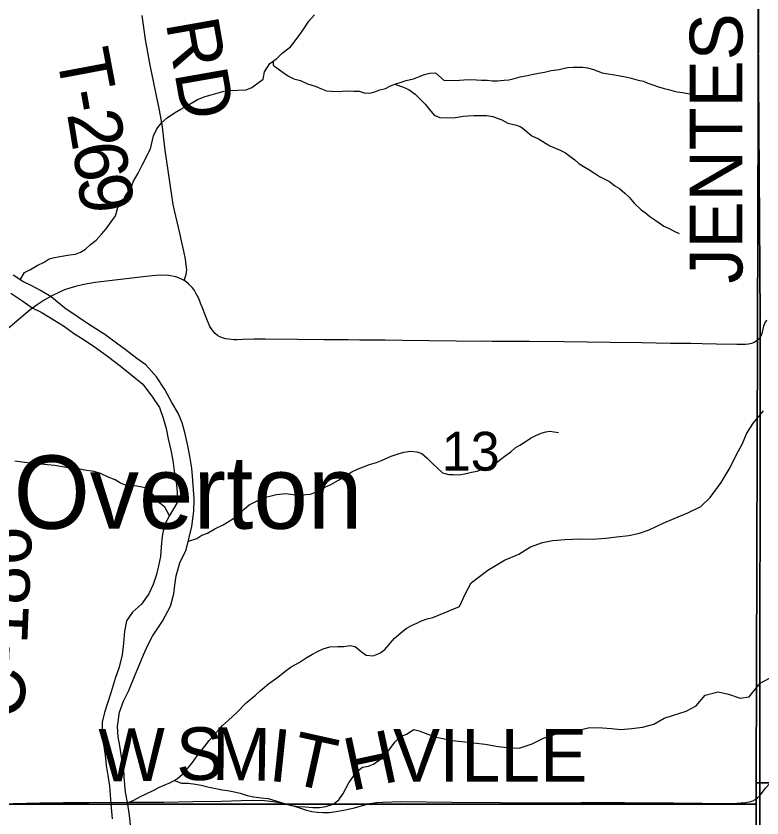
# Model space of a CAD drawing. Extents: x 1985906 to 2360102, y 891258 to 1222054.
# Drawn here: x 2104398 to 2108640, y 1041341 to 1045904 of the extents above; entities that cross this region are included whole.
import ezdxf

# ---------------------------------------------------------------- set-up
doc = ezdxf.new("R2010")
doc.units = 0
for name, color, linetype in [('GM_X_County_Road', 7, 'Continuous'), ('GM_X_County_Road_Text', 7, 'Continuous'), ('GM_X_Major_River', 7, 'Continuous'), ('GM_X_Minor_River', 7, 'Continuous'), ('GM_X_Section', 7, 'Continuous'), ('GM_X_Section_Text', 7, 'Continuous'), ('GM_X_Township', 7, 'Continuous'), ('GM_X_Township_Road', 7, 'Continuous'), ('GM_X_Township_Road_Text', 7, 'Continuous'), ('GM_X_Unincorporated_Text', 7, 'Continuous')]:
    doc.layers.add(name, color=color, linetype=linetype)

msp = doc.modelspace()

# ---------------------------------------------------------------- linework, layer by layer
at = {"layer": 'GM_X_County_Road'}
for points in [[(2105354.5, 1044398.9), (2105331, 1044411), (2105305.9, 1044419.7), (2105265.9, 1044427.5), (2105217.3, 1044429.3), (2105171.3, 1044426.7), (2105119.9, 1044420.4), (2105008.4, 1044407.9), (2104960.2, 1044402.4), (2104911.8, 1044396.6), (2104847, 1044388), (2104782.8, 1044376.9), (2104735.4, 1044366), (2104704.4, 1044356.9), (2104674.1, 1044346), (2104644.3, 1044333.8), (2104600.5, 1044312.2), (2104558, 1044288.1), (2104517.1, 1044261.3), (2104478.1, 1044231.8), (2104390.3, 1044158.3), (2104337.5, 1044113)], [(2105453.9, 1044254.4), (2105453.5, 1044255.6), (2105437, 1044296.4), (2105423.1, 1044324.2), (2105410, 1044345.9), (2105399.6, 1044359.8), (2105379.6, 1044379.8), (2105358, 1044397.1), (2105354.5, 1044398.9)], [(2108628.4, 1044074.7), (2108623.7, 1044068), (2108611.2, 1044056.2), (2108596.7, 1044047.3), (2108580.8, 1044041.2), (2108564.1, 1044037.8), (2108547.4, 1044035.8), (2108497.5, 1044034.6), (2108382.7, 1044037.3), (2108300.8, 1044039.2), (2108235.4, 1044040.3), (2108120.8, 1044041.9), (2107957.3, 1044044.9), (2107777.1, 1044047.1), (2107515.1, 1044050.3), (2107319, 1044052.2), (2107106.6, 1044053.4), (2107073.9, 1044053.5), (2107057.5, 1044053.1), (2106746.3, 1044055.9), (2106596.1, 1044058.2), (2106498, 1044059.2), (2106406.8, 1044060.1), (2106353, 1044060.6), (2106286.1, 1044061.3), (2106215.8, 1044062), (2106148.1, 1044062.7), (2105998.7, 1044064.2), (2105815.1, 1044066), (2105751.5, 1044065), (2105688.3, 1044063.9), (2105655.5, 1044062.7), (2105639, 1044062.9), (2105605.7, 1044065.5), (2105589.2, 1044068.1), (2105572.9, 1044072.5), (2105557.3, 1044078.7), (2105543, 1044087.5), (2105530, 1044098.2), (2105518.6, 1044110.5), (2105508.6, 1044123.9), (2105499.9, 1044138), (2105479.5, 1044188.7), (2105453.9, 1044254.4)], [(2108669.1, 1044174.3), (2108666.2, 1044171.8), (2108659.4, 1044162.3), (2108654.3, 1044153), (2108650, 1044140), (2108640.2, 1044097.9), (2108633.7, 1044082.2), (2108628.4, 1044074.7)]]:
    msp.add_lwpolyline(points, dxfattribs=at)
at = {"layer": 'GM_X_Major_River'}
for points in [[(2105050.1, 1041285), (2105043.7, 1041355), (2105033.4, 1041419.1), (2105021, 1041489.1), (2105012.5, 1041573.2), (2105010.3, 1041623.2), (2104997.9, 1041689.2), (2104987.6, 1041751.3), (2104979.3, 1041803.3), (2104974.9, 1041861.3), (2104986.5, 1041943.5), (2105008.2, 1042005.8), (2105039.8, 1042066), (2105075.3, 1042156.3), (2105099, 1042214.6), (2105122.7, 1042268.8), (2105146.4, 1042325), (2105174.1, 1042375.2), (2105231.6, 1042461.7), (2105277.2, 1042546.1), (2105294.8, 1042616.3), (2105300.5, 1042666.4), (2105308.2, 1042718.5), (2105329.8, 1042792.7), (2105365.4, 1042867.1), (2105383, 1042937.2), (2105396.7, 1042999.4), (2105408.2, 1043087.6), (2105411.8, 1043155.7), (2105407.5, 1043209.8), (2105403.2, 1043261.8), (2105396.8, 1043331.9), (2105386.5, 1043399.9), (2105374.2, 1043457.9), (2105359.8, 1043528), (2105343.4, 1043589.9), (2105319.1, 1043643.9), (2105284.8, 1043705.8), (2105244.4, 1043779.7), (2105196, 1043851.5), (2105135.6, 1043919.2), (2105085.4, 1043955), (2105019.2, 1044006.7), (2104969, 1044042.4), (2104902.7, 1044092.1), (2104816.4, 1044147.7), (2104675.9, 1044243), (2104597.6, 1044306.6), (2104537.4, 1044342.3), (2104487.2, 1044370.1), (2104437.1, 1044393.8), (2104380.9, 1044429.5)], [(2104367.5, 1044327.3), (2104435.7, 1044281.6), (2104489.9, 1044243.9), (2104540, 1044220.2), (2104618.3, 1044172.5), (2104672.5, 1044138.8), (2104724.7, 1044099.1), (2104778.9, 1044065.3), (2104855.1, 1044013.7), (2104925.4, 1043964), (2104989.7, 1043914.3), (2105047.9, 1043866.6), (2105118.3, 1043808.9), (2105174.7, 1043735.2), (2105213, 1043677.3), (2105237.3, 1043611.4), (2105251.6, 1043557.4), (2105263.9, 1043499.3), (2105278.3, 1043433.3), (2105288.6, 1043375.3), (2105296.9, 1043315.3), (2105309.3, 1043253.3), (2105313.6, 1043195.2), (2105311.9, 1043133.1), (2105268.4, 1043058.8), (2105242.6, 1043008.5), (2105229, 1042944.4), (2105223.3, 1042884.2), (2105219.6, 1042828.2), (2105207.9, 1042776), (2105196.2, 1042725.9), (2105178.5, 1042669.7), (2105152.8, 1042617.5), (2105111.1, 1042557.1), (2105059.4, 1042512.8), (2105025.6, 1042462.5), (2105014, 1042404.3), (2105008.3, 1042336.2), (2105000.7, 1042270.1), (2104985.1, 1042199.9), (2104961.4, 1042135.7), (2104937.9, 1042059.4), (2104918.2, 1041995.2), (2104900.5, 1041941), (2104886.8, 1041886.9), (2104887.2, 1041816.8), (2104895.5, 1041760.7), (2104903.8, 1041698.7)], [(2104903.8, 1041698.7), (2104910.2, 1041640.7), (2104920.5, 1041582.6), (2104928.8, 1041524.6), (2104933.1, 1041470.6), (2104939.5, 1041398.5), (2104943.8, 1041336.4)]]:
    msp.add_lwpolyline(points, dxfattribs=at)
at = {"layer": 'GM_X_Minor_River'}
for points in [[(2104421.4, 1044403.8), (2104446.2, 1044445.7), (2104480.1, 1044461.9), (2104518.1, 1044484.2), (2104558.1, 1044504.4), (2104586, 1044522.6), (2104616, 1044530.8), (2104658.1, 1044539), (2104704.1, 1044545.2), (2104736.2, 1044549.4), (2104764.2, 1044561.6), (2104792.1, 1044577.8), (2104822.1, 1044604), (2104854, 1044628.2), (2104883.9, 1044662.5), (2104909.8, 1044692.7), (2104929.7, 1044720.9), (2104963.5, 1044767.3), (2104977.3, 1044815.5), (2105003.2, 1044845.8), (2105021, 1044884), (2105050.8, 1044922.3), (2105066.7, 1044964.5), (2105092.5, 1045010.8), (2105116.3, 1045059.1), (2105132.1, 1045087.3), (2105146, 1045117.4), (2105161.9, 1045149.6), (2105179.5, 1045222), (2105199.4, 1045262.2), (2105225.2, 1045296.5), (2105257.1, 1045324.7), (2105299.1, 1045353), (2105335, 1045375.3), (2105369, 1045393.5), (2105428.9, 1045429.9), (2105472.9, 1045446.2), (2105506.9, 1045456.4), (2105547, 1045466.6), (2105581, 1045476.8), (2105609, 1045480.9), (2105659.1, 1045483.2), (2105707.2, 1045485.4), (2105739.2, 1045497.6), (2105775.1, 1045523.8), (2105803, 1045546.1), (2105810.9, 1045586.3), (2105840.7, 1045634.6), (2105880.6, 1045662.9), (2105910.5, 1045693.1), (2105958.4, 1045729.5), (2105986.3, 1045763.7), (2106012.1, 1045800), (2106034, 1045832.2), (2106063.8, 1045874.5), (2106095.7, 1045910.8)], [(2105859.9, 1045648.2), (2105860.7, 1045624.6), (2105917.1, 1045582.7), (2105947.2, 1045562.8), (2105977.4, 1045546.9), (2106015.5, 1045537), (2106055.7, 1045519.1), (2106099.8, 1045505.3), (2106136, 1045489.4), (2106164.1, 1045479.4), (2106192.2, 1045477.6), (2106226.2, 1045475.7), (2106254.3, 1045477.8), (2106282.3, 1045478), (2106318.4, 1045476.1), (2106348.5, 1045476.3), (2106378.6, 1045468.4), (2106410.6, 1045466.5), (2106438.7, 1045472.7), (2106466.7, 1045484.8), (2106498.7, 1045493), (2106526.7, 1045507.2), (2106558.7, 1045519.4), (2106588.7, 1045527.6), (2106616.7, 1045537.7), (2106658.7, 1045548), (2106686.7, 1045558.1), (2106720.7, 1045572.3), (2106750.7, 1045578.5), (2106782.8, 1045580.7), (2106832.5, 1045537.4)], [(2106832.5, 1045537.4), (2106920.8, 1045538.6), (2106944.9, 1045540.9), (2106985, 1045543.4), (2107017.2, 1045541.9), (2107045.3, 1045540.2), (2107077.5, 1045538.7), (2107105.6, 1045535), (2107135.7, 1045535.4), (2107173.8, 1045539.9), (2107199.9, 1045542.3), (2107226, 1045546.7), (2107266, 1045559.2), (2107298, 1045563.7), (2107332.1, 1045572.2), (2107370.1, 1045578.7), (2107404.2, 1045585.2), (2107442.2, 1045593.7), (2107486.3, 1045600.3), (2107510.3, 1045606.6), (2107534.4, 1045611), (2107566.5, 1045613.4), (2107620.7, 1045614.1), (2107648.9, 1045610.5), (2107683.1, 1045600.9), (2107731.6, 1045581.5), (2107765.8, 1045575.9), (2107789.9, 1045572.2), (2107834.2, 1045564.8), (2107864.4, 1045559.2), (2107896.6, 1045551.6), (2107937, 1045540.1), (2107967.1, 1045534.5), (2107991.4, 1045522.8), (2108019.6, 1045513.1), (2108051.9, 1045501.5), (2108084.2, 1045491.9), (2108108.3, 1045486.2), (2108134.5, 1045478.6), (2108158.7, 1045472.9), (2108188.9, 1045469.2), (2108219.1, 1045463.7), (2108245.3, 1045458), (2108273.5, 1045450.3), (2108303.7, 1045442.7)], [(2106551.8, 1045516.8), (2106600.8, 1045499.5), (2106633, 1045483.6), (2106667.2, 1045459.7), (2106697.4, 1045429.7), (2106725.6, 1045403.7), (2106749.8, 1045371.7), (2106776, 1045339.7), (2106808.1, 1045327.8)], [(2106808.1, 1045327.8), (2106879.4, 1045325.4), (2106911.5, 1045329.8), (2106941.6, 1045334.3), (2106967.6, 1045336.6), (2107001.7, 1045339.1), (2107025.8, 1045339.4), (2107052, 1045337.7), (2107076.1, 1045338), (2107110.3, 1045332.5), (2107134.5, 1045322.8), (2107160.7, 1045313.1), (2107195.1, 1045295.5), (2107243.4, 1045284.1), (2107269.7, 1045274.4), (2107296.1, 1045252.7), (2107330.6, 1045223.1), (2107369, 1045205.6), (2107409.4, 1045182), (2107433.7, 1045166.3), (2107492.3, 1045141), (2107522.6, 1045125.4), (2107547, 1045107.7), (2107575.4, 1045086), (2107599.7, 1045066.2), (2107632.1, 1045044.6), (2107656.4, 1045030.9), (2107688.8, 1045011.3), (2107717.2, 1044991.6), (2107743.4, 1044977.9), (2107773.8, 1044962.2), (2107804.2, 1044938.6), (2107830.5, 1044922.9), (2107861, 1044897.2), (2107885.4, 1044873.5), (2107913.9, 1044839.8), (2107952.6, 1044802.2), (2107978.9, 1044784.5), (2108003.3, 1044764.7), (2108031.6, 1044745), (2108056, 1044727.3), (2108082.3, 1044709.6), (2108108.6, 1044697.9), (2108140.9, 1044680.3), (2108169.2, 1044666.7)], [(2106920.3, 1042545.4), (2106953.8, 1042617.8), (2106987.4, 1042680.1), (2107080.9, 1042750.9), (2107176.5, 1042807.7), (2107258.2, 1042842.4), (2107323.9, 1042884.9), (2107391.7, 1042909.5), (2107449.6, 1042919.9), (2107521.6, 1042926.5), (2107603.6, 1042929.1), (2107675.6, 1042927.6), (2107751.5, 1042934.2), (2107813.5, 1042940.7), (2107883.4, 1042949.2), (2107943.3, 1042961.7), (2107999.2, 1042980.2), (2108078.9, 1043018.8), (2108140.7, 1043045.3), (2108218.5, 1043077.9), (2108292.2, 1043114.5), (2108345.8, 1043165), (2108409.3, 1043249.6), (2108458.7, 1043336.1), (2108496.1, 1043410.4), (2108527.7, 1043468.8), (2108555.3, 1043531), (2108592.9, 1043589.4), (2108648.4, 1043657.9)], [(2106822.7, 1043305.9), (2106859.6, 1043295.2), (2106883.7, 1043295.5), (2106917.9, 1043294), (2106958, 1043300.5), (2106988, 1043309), (2107020, 1043315.4), (2107046, 1043323.8), (2107078, 1043334.2), (2107103.9, 1043348.6), (2107127.8, 1043363), (2107155.7, 1043383.4), (2107179.5, 1043401.8), (2107211.4, 1043424.3), (2107237.2, 1043446.7), (2107263.1, 1043463.1), (2107293, 1043481.5), (2107324.8, 1043502), (2107354.7, 1043518.5), (2107384.7, 1043530.9), (2107410.7, 1043539.3), (2107434.8, 1043541.6), (2107483.1, 1043534.2)], [(2105377.9, 1042916.9), (2105426, 1042932.3), (2105453.9, 1042950.5), (2105485.9, 1042962.7), (2105527.9, 1042987), (2105575.9, 1043009.3), (2105625.8, 1043039.7), (2105667.7, 1043070), (2105695.6, 1043098.2), (2105723.5, 1043122.4), (2105761.5, 1043142.7), (2105817.5, 1043167), (2105849.5, 1043175.2), (2105879.5, 1043181.3), (2105931.6, 1043187.6), (2105985.8, 1043179.8), (2106019.8, 1043180), (2106071.9, 1043184.2), (2106119.9, 1043202.5), (2106153.9, 1043222.8), (2106187.8, 1043239), (2106231.8, 1043263.3), (2106267.7, 1043285.5), (2106307.7, 1043311.8), (2106343.7, 1043328), (2106373.7, 1043340.2), (2106407.7, 1043352.4), (2106447.7, 1043364.6), (2106475.7, 1043374.8), (2106531.7, 1043399.2), (2106571.7, 1043413.4), (2106603.7, 1043423.6), (2106641.7, 1043427.8), (2106677.8, 1043423.9), (2106705.9, 1043416), (2106736.1, 1043388), (2106764.3, 1043360.1), (2106822.7, 1043305.9)], [(2105269.8, 1043061.2), (2105244.7, 1043110.2), (2105216.5, 1043132.2), (2105186.3, 1043168.2), (2105160.1, 1043198.1), (2105131.9, 1043220.1), (2105085.7, 1043229.9), (2105051.7, 1043233.8), (2105019.6, 1043235.7), (2104991.5, 1043245.6), (2104961.3, 1043265.5), (2104921.2, 1043281.4), (2104879, 1043301.3), (2104842.8, 1043313.2), (2104786.7, 1043320.9), (2104742.6, 1043330.8), (2104694.4, 1043334.5), (2104618.2, 1043346.2), (2104576.1, 1043350.1), (2104481.9, 1043359.7), (2104445.8, 1043363.5), (2104391.7, 1043371.3)], [(2105032, 1041426.7), (2105067, 1041443), (2105105, 1041463.2), (2105135, 1041477.4), (2105181, 1041499.7), (2105212.9, 1041515.9), (2105240.9, 1041528.1), (2105276.9, 1041542.3), (2105314.9, 1041564.6), (2105344.8, 1041590.8), (2105376.7, 1041627.1), (2105400.6, 1041657.3), (2105428.4, 1041695.6), (2105472.2, 1041750), (2105496.1, 1041782.2), (2105547.9, 1041838.7), (2105571.8, 1041866.9), (2105605.7, 1041897.2), (2105653.6, 1041941.6), (2105707.4, 1041996), (2105759.3, 1042040.4), (2105787.2, 1042064.7), (2105833.1, 1042105), (2105887, 1042143.4), (2105926.9, 1042175.7), (2105962.8, 1042202), (2106008.8, 1042226.3), (2106048.7, 1042252.6), (2106084.7, 1042272.8), (2106112.6, 1042289), (2106144.6, 1042303.2), (2106182.7, 1042315.4), (2106228.7, 1042317.6), (2106262.8, 1042317.8), (2106298.8, 1042322), (2106326.9, 1042316.1), (2106361.1, 1042288.1), (2106389.3, 1042268.2), (2106429.4, 1042264.3), (2106467.4, 1042278.6), (2106495.3, 1042300.8), (2106519.2, 1042329), (2106549.1, 1042363.3), (2106587, 1042395.6), (2106616.9, 1042419.8), (2106646.9, 1042436), (2106676.9, 1042450.2), (2106704.9, 1042462.3), (2106736.9, 1042474.5), (2106768.9, 1042482.7), (2106920.3, 1042545.4)], [(2106879.6, 1041782.1), (2106933.6, 1041776.5), (2107065.7, 1041761.5), (2107139.8, 1041748.1), (2107193.8, 1041742.5), (2107259.8, 1041739), (2107333.7, 1041763.5), (2107397.4, 1041796.1), (2107465.3, 1041818.6), (2107535.2, 1041823.2), (2107589.1, 1041839.6), (2107659, 1041856.1), (2107733, 1041854.7), (2107785, 1041851.1), (2107837, 1041845.5), (2107901, 1041849.9), (2107960.9, 1041858.4), (2108024.8, 1041874.9), (2108084.6, 1041909.4), (2108136.4, 1041925.8), (2108210.3, 1041948.4), (2108266.1, 1041978.9), (2108317.6, 1042039.3), (2108391.5, 1042059.9), (2108449.6, 1042046.3), (2108515.7, 1042022.8), (2108567.7, 1042031.2), (2108631.1, 1042107.8), (2108682.9, 1042136.2)], [(2105298.7, 1041555.1), (2105339.1, 1041538.6), (2105377.1, 1041538.8), (2105419.3, 1041532.9), (2105451.3, 1041527.1), (2105495.5, 1041517.2), (2105571.7, 1041501.5), (2105599.8, 1041497.6), (2105629.9, 1041491.8), (2105672, 1041481.9), (2105712.1, 1041470), (2105750.3, 1041462.2), (2105792.4, 1041456.3), (2105832.5, 1041452.5), (2105874.6, 1041438.7), (2105924.8, 1041422.8), (2105962.9, 1041413), (2106003, 1041407.1), (2106043.1, 1041405.3), (2106085.2, 1041401.5), (2106123.3, 1041401.7), (2106159.3, 1041405.8), (2106201.4, 1041420.1), (2106233.3, 1041444.3), (2106259.2, 1041480.6), (2106290.9, 1041540.9), (2106312.8, 1041573.2), (2106334.7, 1041603.4), (2106368.6, 1041629.6), (2106402.6, 1041635.8), (2106430.6, 1041648), (2106462.6, 1041670.2), (2106498.5, 1041700.5), (2106524.3, 1041734.7), (2106554.2, 1041775), (2106582.1, 1041803.3), (2106618.1, 1041817.5), (2106660, 1041843.8), (2106690.1, 1041837.9), (2106718.2, 1041826), (2106746.3, 1041816.1), (2106778.5, 1041802.2), (2106879.6, 1041782.1)]]:
    msp.add_lwpolyline(points, dxfattribs=at)
at = {"layer": 'GM_X_Section'}
for points in [[(2108626.2, 1046812.6), (2114343.5, 1046864.4), (2114352.9, 1041541.2), (2108607.2, 1041541.2), (2108623.2, 1046652.5)], [(2102970.3, 1046741.1), (2108623.2, 1046652.5), (2108607.2, 1041541.2), (2108608, 1041419.2), (2103020.2, 1041420.1)], [(2108607.2, 1041541.2), (2114352.9, 1041541.2), (2114398.2, 1036216.2), (2108612.2, 1036278.1), (2108614.1, 1036304.1), (2108608, 1041419.2)], [(2108608, 1041419.2), (2108614.1, 1036304.1), (2103084, 1036099.3), (2103020.2, 1041420.1)]]:
    msp.add_lwpolyline(points, close=True, dxfattribs=at)
at = {"layer": 'GM_X_Township'}
for points in [[(2108590.2, 1057156.5), (2108639.5, 1052043.3), (2108637.1, 1049741.1), (2108630.4, 1047484.6), (2108627.5, 1046838.9), (2108612.5, 1046641.2), (2108630.4, 1044190.7), (2108630.3, 1044082.6), (2108629.3, 1041511.6), (2108630.8, 1034179.2), (2108627, 1033545.8), (2108551.5, 1029433), (2108528.9, 1027031.5), (2108514.5, 1025497.4), (2103772.2, 1025425.9), (2103219.4, 1025417.6), (2103068.8, 1025432.7), (2097635.3, 1025405.6), (2096078.3, 1025395), (2095094.6, 1025388.3), (2092097.4, 1025367.8)], [(2108630.8, 1034179.2), (2108629.3, 1041511.6), (2108630.3, 1044082.6), (2108630.4, 1044190.7), (2108612.5, 1046641.2), (2108627.5, 1046838.9), (2108630.4, 1047484.6), (2108637.1, 1049741.1), (2108639.5, 1052043.3), (2108590.2, 1057156.5)]]:
    msp.add_lwpolyline(points, dxfattribs=at)
at = {"layer": 'GM_X_Township_Road'}
for points in [[(2105354.5, 1044398.9), (2105358.4, 1044411.5), (2105365.4, 1044434), (2105369.3, 1044459.7), (2105367.8, 1044474.4), (2105361.7, 1044520.8), (2105351.4, 1044566.2), (2105339, 1044625.3), (2105329.7, 1044668.8), (2105315.6, 1044725.2), (2105306.4, 1044766.1), (2105299.1, 1044798.3), (2105291.7, 1044831.2), (2105281.2, 1044897.5), (2105246.3, 1045141.3), (2105228, 1045287.6), (2105213.7, 1045368), (2105161.2, 1045625.2), (2105134.9, 1045770.7), (2105116, 1045907.2)], [(2108631.3, 1041472.3), (2108652.9, 1041500.5), (2108663.3, 1041513.5), (2108679.8, 1041530.9), (2108690.2, 1041538.7), (2108705.9, 1041546.5), (2108719.7, 1041551.7), (2108738.9, 1041556.9), (2108755.4, 1041559.5), (2108784, 1041560.4), (2109083.4, 1041552.3), (2109263.9, 1041551.9), (2109395.1, 1041550.3), (2109558.8, 1041548.2), (2109771.6, 1041547), (2109919.1, 1041545.8), (2110001.2, 1041545.8), (2110116.1, 1041545.4), (2110444.4, 1041544.1), (2110657.8, 1041542.2), (2110887.6, 1041540.8), (2111084.6, 1041539.8), (2111330.6, 1041539.7), (2111533.8, 1041541.4)], [(2103898.9, 1041413.8), (2103925.9, 1041414.1), (2104040.8, 1041416.1), (2104303.3, 1041422.7), (2104533.1, 1041427.8), (2104668.5, 1041428.5)], [(2104668.5, 1041428.5), (2104812.3, 1041429.3), (2105042, 1041431.2), (2105237.9, 1041431.9)], [(2105237.9, 1041431.9), (2105239, 1041431.9), (2105403.1, 1041434.4), (2105565.7, 1041437), (2105678.8, 1041441.3), (2105744.4, 1041442.9), (2105810.3, 1041440.3), (2105859.4, 1041435.4), (2105908.1, 1041427.7), (2105940.2, 1041420.5), (2105987.5, 1041406.3), (2106049.5, 1041386), (2106081, 1041378.8), (2106112.8, 1041374.1), (2106145.1, 1041371.6), (2106178.1, 1041372.5), (2106218.9, 1041377.7), (2106270.1, 1041388.1), (2106323.1, 1041399.4), (2106381.3, 1041415.9), (2106410.8, 1041422.8), (2106448.1, 1041428.9), (2106484.6, 1041431.5), (2106585.4, 1041434.9), (2106875.7, 1041430.5), (2107153.7, 1041428.6), (2107284.5, 1041427.8), (2107382.5, 1041428), (2107612, 1041429.5), (2107858, 1041429.4), (2108136.9, 1041427.6), (2108301, 1041426), (2108448.8, 1041423.4), (2108497.8, 1041424.7), (2108546.2, 1041429.2), (2108568.6, 1041432.6), (2108577.7, 1041434.8), (2108589, 1041439.6), (2108602.3, 1041446.2), (2108615.6, 1041456.5), (2108631.3, 1041472.3)]]:
    msp.add_lwpolyline(points, dxfattribs=at)

# ---------------------------------------------------------------- texts
at = {"layer": 'GM_X_County_Road_Text'}
msp.add_text('C-186', height=300, rotation=87.5692, dxfattribs=at).set_placement((2104443.1, 1041903.7))
at = {"layer": 'GM_X_Section_Text'}
msp.add_text('13', height=221, rotation=0, dxfattribs=at).set_placement((2106819.5, 1043317.6))
at = {"layer": 'GM_X_Township_Road_Text'}
for s, rotation, p in [('JENTES', 90, (2108529.7, 1044382.1)), ('RD', 279.9451, (2105248.4, 1045867.4)), ('T', 280.6334, (2104624.9, 1045688.8)), ('-', 280.027, (2104666.2, 1045469.1)), ('2', 279.3066, (2104687.5, 1045348.8)), ('6', 278.5665, (2104717.2, 1045167.4)), ('9', 278.2346, (2104744.7, 1044985.1)), ('W', 0.9407, (2104870.6, 1041547.7)), ('S', 0.8933, (2105310.5, 1041554.9)), ('M', 359.1582, (2105510.5, 1041558.1)), ('I', 353.9391, (2105828.8, 1041553.7)), ('H', 12.1463, (2106301.5, 1041493.1)), ('V', 0.1749, (2106543.1, 1041546.9)), ('I', 0, (2106806.9, 1041547.7)), ('L', 0, (2106930.1, 1041547.7)), ('L', 0, (2107154.5, 1041547.7)), ('E', 0, (2107378.9, 1041547.7)), ('T', 347.494, (2105942.5, 1041542.2))]:
    msp.add_text(s, height=300, rotation=rotation, dxfattribs=at).set_placement(p)
at = {"layer": 'GM_X_Unincorporated_Text'}
msp.add_text('Overton', height=417, rotation=0, dxfattribs=at).set_placement((2104384.2, 1042987))

doc.saveas('drawing.dxf')
